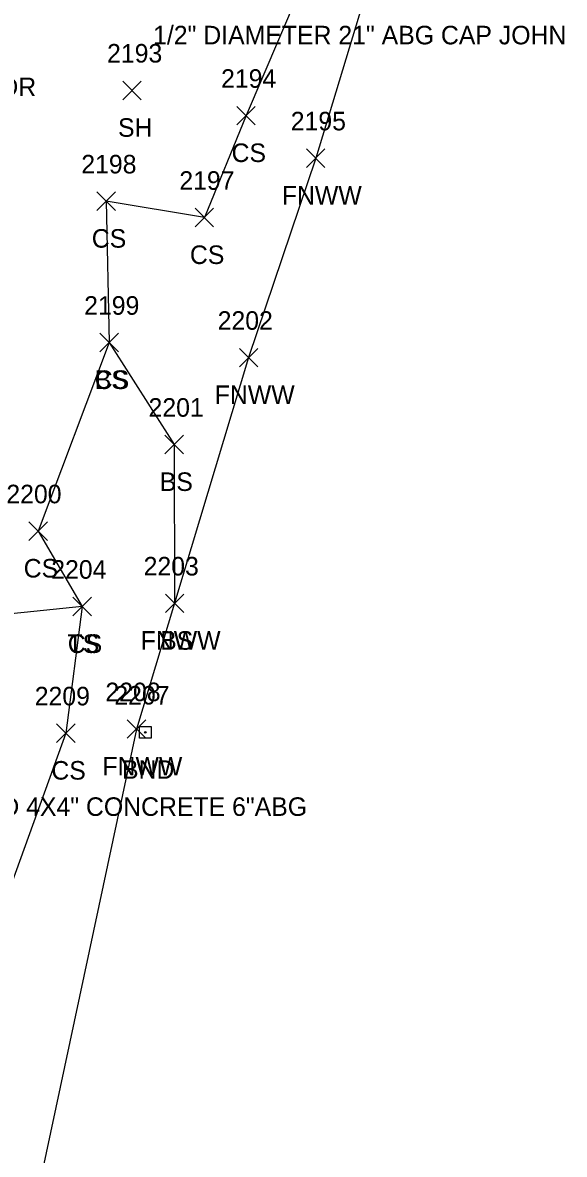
# Model space of a CAD drawing. Extents: x 1483143 to 1488182, y 802902 to 807581.
# Drawn here: x 1488062.4 to 1488120.8, y 806784.9 to 806906.9 of the extents above; entities that cross this region are included whole.
import ezdxf

# ---------------------------------------------------------------- set-up
doc = ezdxf.new("R2010")
doc.units = 0
for name, color, linetype in [('L_A', 7, 'Continuous'), ('L_I', 7, 'Continuous'), ('L_TIC', 7, 'Continuous'), ('LELB', 7, 'Continuous'), ('LFNC', 7, 'Continuous'), ('M_A', 7, 'Continuous'), ('M_C', 7, 'Continuous'), ('M_I', 7, 'Continuous'), ('MHBP', 7, 'Continuous')]:
    doc.layers.add(name, color=color, linetype=linetype)

msp = doc.modelspace()

# ---------------------------------------------------------------- linework, layer by layer
at = {"layer": 'L_TIC'}
for points in [[(1488073.17, 806898.55), (1488075.17, 806900.55)], [(1488075.17, 806898.55), (1488073.17, 806900.55)], [(1488085.46, 806895.83), (1488087.46, 806897.83)], [(1488087.46, 806895.83), (1488085.46, 806897.83)], [(1488092.97, 806891.24), (1488094.97, 806893.24)], [(1488094.97, 806891.24), (1488092.97, 806893.24)], [(1488070.39, 806886.6), (1488072.39, 806888.6)], [(1488072.39, 806886.6), (1488070.39, 806888.6)], [(1488080.97, 806884.84), (1488082.97, 806886.84)], [(1488082.97, 806884.84), (1488080.97, 806886.84)], [(1488070.71, 806871.37), (1488072.71, 806873.37)], [(1488072.71, 806871.37), (1488070.71, 806873.37)], [(1488070.71, 806871.37), (1488072.71, 806873.37)], [(1488072.71, 806871.37), (1488070.71, 806873.37)], [(1488085.74, 806869.75), (1488087.74, 806871.75)], [(1488087.74, 806869.75), (1488085.74, 806871.75)], [(1488077.72, 806860.38), (1488079.72, 806862.38)], [(1488079.72, 806860.38), (1488077.72, 806862.38)], [(1488063.05, 806851.05), (1488065.05, 806853.05)], [(1488065.05, 806851.05), (1488063.05, 806853.05)], [(1488077.76, 806843.27), (1488079.76, 806845.27)], [(1488079.76, 806843.27), (1488077.76, 806845.27)], [(1488077.76, 806843.27), (1488079.76, 806845.27)], [(1488079.76, 806843.27), (1488077.76, 806845.27)], [(1488067.8, 806842.92), (1488069.8, 806844.92)], [(1488069.8, 806842.92), (1488067.8, 806844.92)], [(1488067.8, 806842.92), (1488069.8, 806844.92)], [(1488069.8, 806842.92), (1488067.8, 806844.92)], [(1488073.64, 806829.72), (1488075.64, 806831.72)], [(1488075.64, 806829.72), (1488073.64, 806831.72)], [(1488066.03, 806829.27), (1488068.03, 806831.27)], [(1488068.03, 806829.27), (1488066.03, 806831.27)]]:
    msp.add_lwpolyline(points, dxfattribs=at)
at = {"layer": 'LELB'}
for points in [[(1488107.24, 807063.62), (1488102.78, 807019.53), (1488102.52, 806993.48), (1488098.25, 806971.93), (1488100.18, 806941.81), (1488099.28, 806926.81), (1488086.46, 806896.83), (1488081.97, 806885.84), (1488071.39, 806887.6), (1488071.71, 806872.37), (1488064.05, 806852.05), (1488068.8, 806843.92), (1488067.03, 806830.27), (1488057.62, 806804.31), (1488039.63, 806814.37), (1488034.14, 806816.99), (1488041.4, 806825.04)], [(1488071.71, 806872.37), (1488078.72, 806861.38), (1488078.76, 806844.27)], [(1488068.8, 806843.92), (1488055.88, 806842.6), (1488050.09, 806819.44), (1488041.4, 806825.04)]]:
    msp.add_lwpolyline(points, dxfattribs=at)
at = {"layer": 'LFNC'}
msp.add_lwpolyline([(1488105.96, 806931.77), (1488093.97, 806892.24), (1488086.74, 806870.75), (1488078.76, 806844.27), (1488074.64, 806830.72), (1488062.83, 806775.27), (1488057.88, 806751.49), (1488052.32, 806724.88), (1488045.16, 806690.9), (1488036.14, 806648.33), (1488029.99, 806618.82), (1488025.33, 806595.98), (1488015.01, 806545.3), (1488004.88, 806498.25), (1488001.38, 806481.96), (1487997.71, 806465.14), (1487995.36, 806451.92), (1487987.25, 806418.51), (1487973.91, 806378.22)], dxfattribs=at)
at = {"layer": 'MHBP'}
msp.add_lwpolyline([(1488074.98, 806830.98), (1488076.23, 806830.98), (1488076.23, 806829.73), (1488074.98, 806829.73)], close=True, dxfattribs=at)
msp.add_circle((1488075.6, 806830.36), 0.0833, dxfattribs=at)

# ---------------------------------------------------------------- texts
at = {"layer": 'L_A'}
for s, p in [('WDR', (1488057.45, 806898.93)), ('SH', (1488072.66, 806894.55)), ('CS', (1488084.9, 806891.83)), ('FNWW', (1488090.32, 806887.24)), ('CS', (1488069.83, 806882.6)), ('CS', (1488080.41, 806880.84)), ('CS', (1488070.15, 806867.37)), ('BS', (1488070.15, 806867.37)), ('FNWW', (1488083.09, 806865.75)), ('BS', (1488077.16, 806856.38)), ('CS', (1488062.49, 806847.05)), ('BS', (1488077.2, 806839.27)), ('TS', (1488067.21, 806838.92)), ('CS', (1488067.24, 806838.92)), ('FNWW', (1488075.1, 806839.27)), ('CS', (1488065.47, 806825.27)), ('FNWW', (1488070.98, 806825.72))]:
    msp.add_text(s, height=2, dxfattribs=at).set_placement(p)
at = {"layer": 'L_I'}
for s, p in [('2193', (1488071.48, 806902.55)), ('2194', (1488083.77, 806899.83)), ('2195', (1488091.28, 806895.24)), ('2198', (1488068.7, 806890.6)), ('2197', (1488079.27, 806888.84)), ('2199', (1488069.01, 806875.37)), ('2199', (1488069.01, 806875.37)), ('2202', (1488083.4, 806873.75)), ('2201', (1488075.95, 806864.38)), ('2200', (1488060.62, 806855.05)), ('2204', (1488065.46, 806846.92)), ('2204', (1488065.46, 806846.92)), ('2203', (1488075.42, 806847.27)), ('2203', (1488075.42, 806847.27)), ('2209', (1488063.68, 806833.27)), ('2208', (1488071.3, 806833.72))]:
    msp.add_text(s, height=2, dxfattribs=at).set_placement(p)
at = {"layer": 'M_A'}
msp.add_text('BND', height=2, dxfattribs=at).set_placement((1488073.09, 806825.36))
at = {"layer": 'M_C'}
for s, p in [('1/2" DIAMETER 21" ABG CAP JOHN', (1488076.44, 806904.51)), ('VTHD 4X4" CONCRETE 6"ABG', (1488054.73, 806821.36))]:
    msp.add_text(s, height=2, dxfattribs=at).set_placement(p)
at = {"layer": 'M_I'}
msp.add_text('2207', height=2, dxfattribs=at).set_placement((1488072.26, 806833.36))

doc.saveas('drawing.dxf')
